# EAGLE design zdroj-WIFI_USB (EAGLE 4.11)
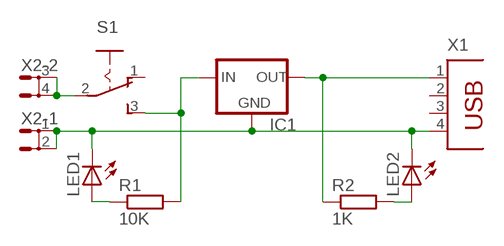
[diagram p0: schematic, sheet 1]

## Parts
IC1  78XXS  [78XXS]
LED1  LED3MM  [LED3MM]
LED2  LED3MM  [LED3MM]
R1  10K  R-EU_0207/10  [0207/10]
R2  1K  R-EU_0207/10  [0207/10]
S1  255SB  [255SB]
X1  PN87520  [PN87520]
X2  SH5-2  [SH5-2]

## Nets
GND: IC1.GND LED1.K(C) LED2.K(C) X1.4 X2.1 X2.2
N$1: IC1.IN R1.2 S1.3(S)
N$3: IC1.OUT R2.1 X1.1
N$4: LED1.A R1.1
N$5: LED2.A R2.2
N$7: S1.2(P) X2.3 X2.4
Unconnected: S1.1(O) X1.2 X1.3

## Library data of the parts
IC1 = v-reg:78XXS: VOLTAGE REGULATOR
LED1 LED2 = led:LED: LED
R1 R2 = rcl:R-EU_: RESISTOR, European symbol
S1 = switch:255SB: SLIDING SWITCH distributor Buerklin, 11G810
X1 = con-berg:PN87520: BERG
X2 = con-rib:SH5-2: RIBBON CABLE CONNECTOR

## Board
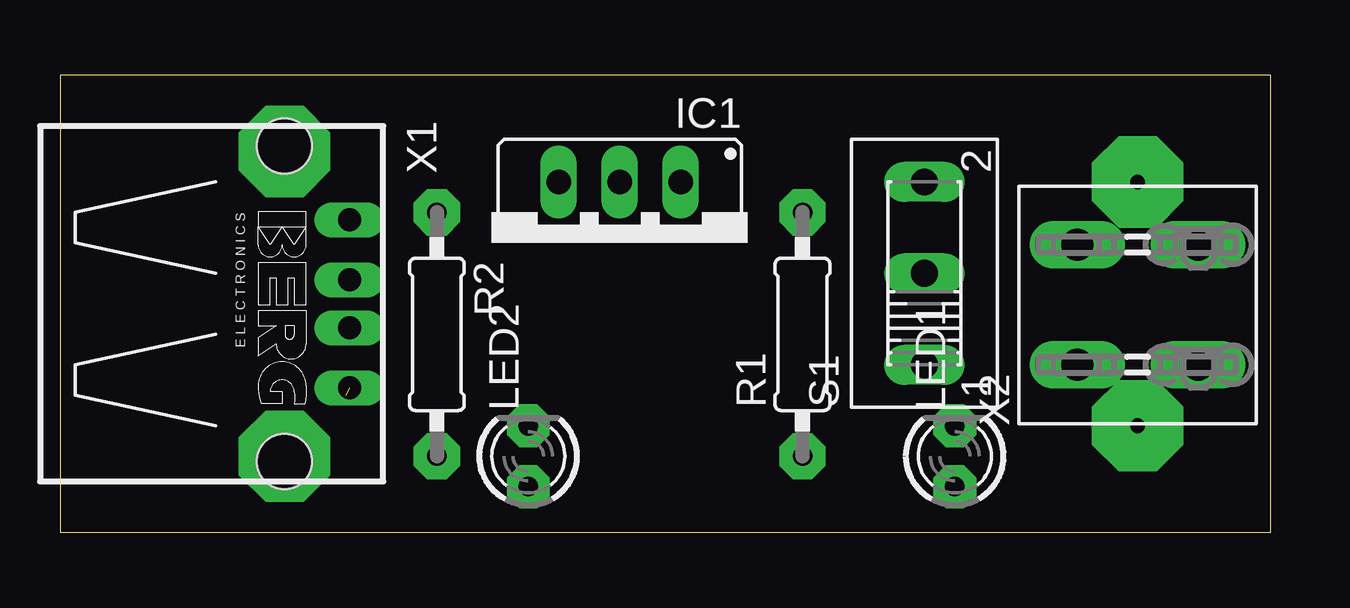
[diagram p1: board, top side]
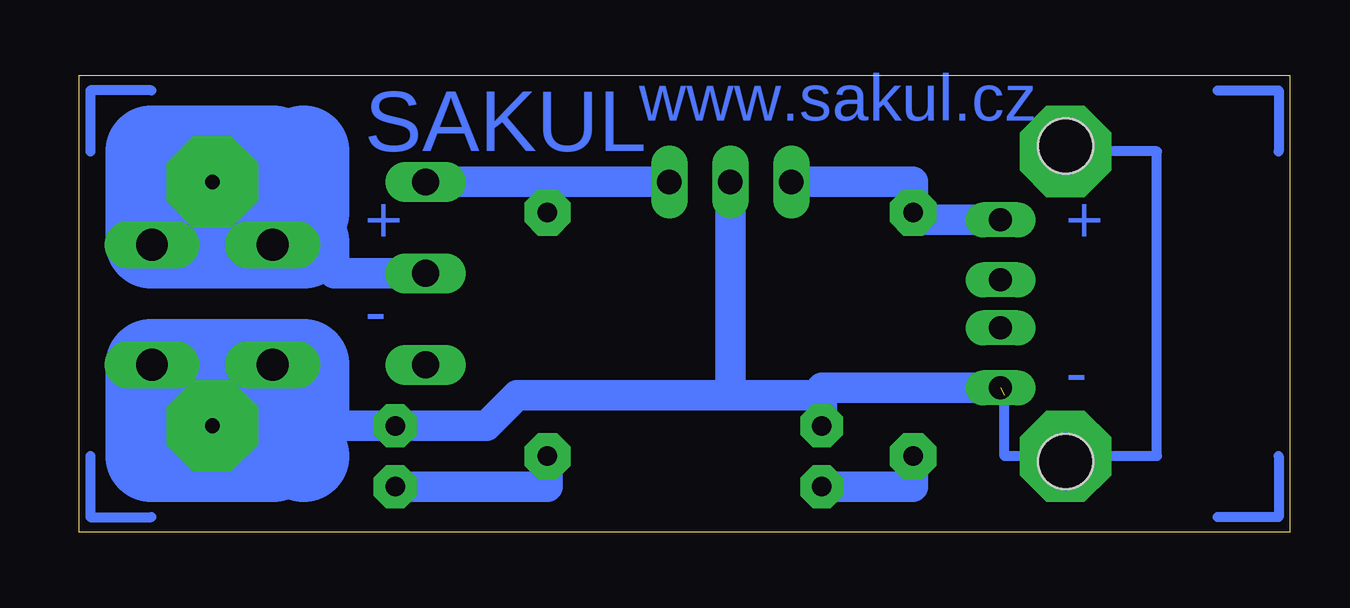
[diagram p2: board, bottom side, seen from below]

Size 50.47 x 19.04 mm. Coordinates in mm from the lower left corner, seen from the top.
Outline: 0,0 50.47,0 50.47,19.04 0,19.04 0,0
Copper layers (1*16): Top 0.035mm / dielectric 1.5mm / Bottom 0.035mm
Design rules "default": minimum track width 10mil, minimum drill 24mil, track to track 8mil, track to pad 8mil, pad to pad 8mil, via to via 8mil, smd to smd 8mil, copper to edge 40mil, drill to drill 8mil, minimum pad ring 10mil, minimum via ring 8mil, stop-mask expansion 4mil, vias tented up to drill 0mil, thermal gap 10mil

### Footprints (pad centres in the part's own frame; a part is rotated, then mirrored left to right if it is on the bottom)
78XXS = drill 1.016 long: GND 0,-2.54; IN -2.54,-2.54; OUT 2.54,-2.54
LED3MM = drill 0.813 pad 1.778 octagon: A -1.27,0; K 1.27,0
0207/10 = drill 0.813 pad 1.93 octagon: 1 -5.08,0; 2 5.08,0
255SB = drill 1.118 long: 1 -3.81,0; 2 0,0; 3 3.81,0
PN87520 = drill 0.95 long: 1 -3.5,2.71; 2 -1,2.71; 3 1,2.71; 4 3.5,2.71 | hole 2.3: -6.57,0; 6.57,0
SH5-2 = drill 1.321 long: 1 0,-2.515; 2 0,2.515; 3 5.004,-2.515; 4 5.004,2.515

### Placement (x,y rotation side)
IC1  23.33,12.06 180 top
LED1  37.3,3.17 90 top
LED2  19.52,3.17 90 top
R1  30.95,8.25 90 top
R2  15.71,8.25 270 top
S1  36.03,10.79 90 top
X1  9.36,9.52 270 top
X2  44.92,6.98 90 top

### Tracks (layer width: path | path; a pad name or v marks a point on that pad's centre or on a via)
GND  (via drill 0.61 pad 3.81)  (1 unrouted)
  Bottom 0.406: 11.9,5.71 11.9,3.17 v9.36,3.17 5.55,3.17 5.55,15.87 v9.36,15.87
  Bottom 1.27: X1.4 19.52,6.02 19.52,5.71 | 19.52,5.71 LED2.K | X2.1 X2.2 41.11,6.98 39.84,6.98 39.84,4.44 LED1.K 33.49,4.44 32.22,5.71 23.33,5.71 | 23.33,5.71 IC1.GND | 19.52,5.71 23.33,5.71
  Bottom 3.81: 41.11,6.98 47.46,6.98 47.46,3.17 42.38,3.17 42.38,4.44 41.11,3.17
N$1
  Bottom 1.27: IC1.IN 30.95,14.6 | 30.95,14.6 R1.2 | 30.95,14.6 S1.3
N$2
  Bottom 0.406: 3.01,18.41 0.47,18.41 0.47,15.87
N$3
  Bottom 1.27: X1.1 15.71,13.02 R2.1 15.71,14.6 IC1.OUT
N$4
  Bottom 1.27: LED1.A 30.95,1.9 R1.1
N$5
  Bottom 1.27: LED2.A 15.71,1.9 R2.2
N$6
  Bottom 0.406: 0.47,3.17 0.47,0.63 3.01,0.63
N$7
  Bottom 1.27: X2.4 42.38,11.98 42.38,12.06 | X2.4 X2.3 | X2.4 39.84,11.98 39.84,10.79 S1.2
  Bottom 3.81: 42.38,12.06 42.38,15.87 47.46,15.87 47.46,12.06 41.11,12.06
N$8
  Bottom 0.406: 47.46,18.41 50,18.41 50,15.87
N$9  (via drill 0.61 pad 3.81)
  other vias: 44.92,14.6
N$10  (via drill 0.61 pad 3.81)
  other vias: 44.92,4.44
N$11
  Bottom 3.81: 41.11,13.33 41.11,15.87
N$12
  Bottom 0.406: 50,3.17 50,0.63 47.46,0.63

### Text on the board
Bottom: www.sakul.cz | SAKUL | + | + | - | -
